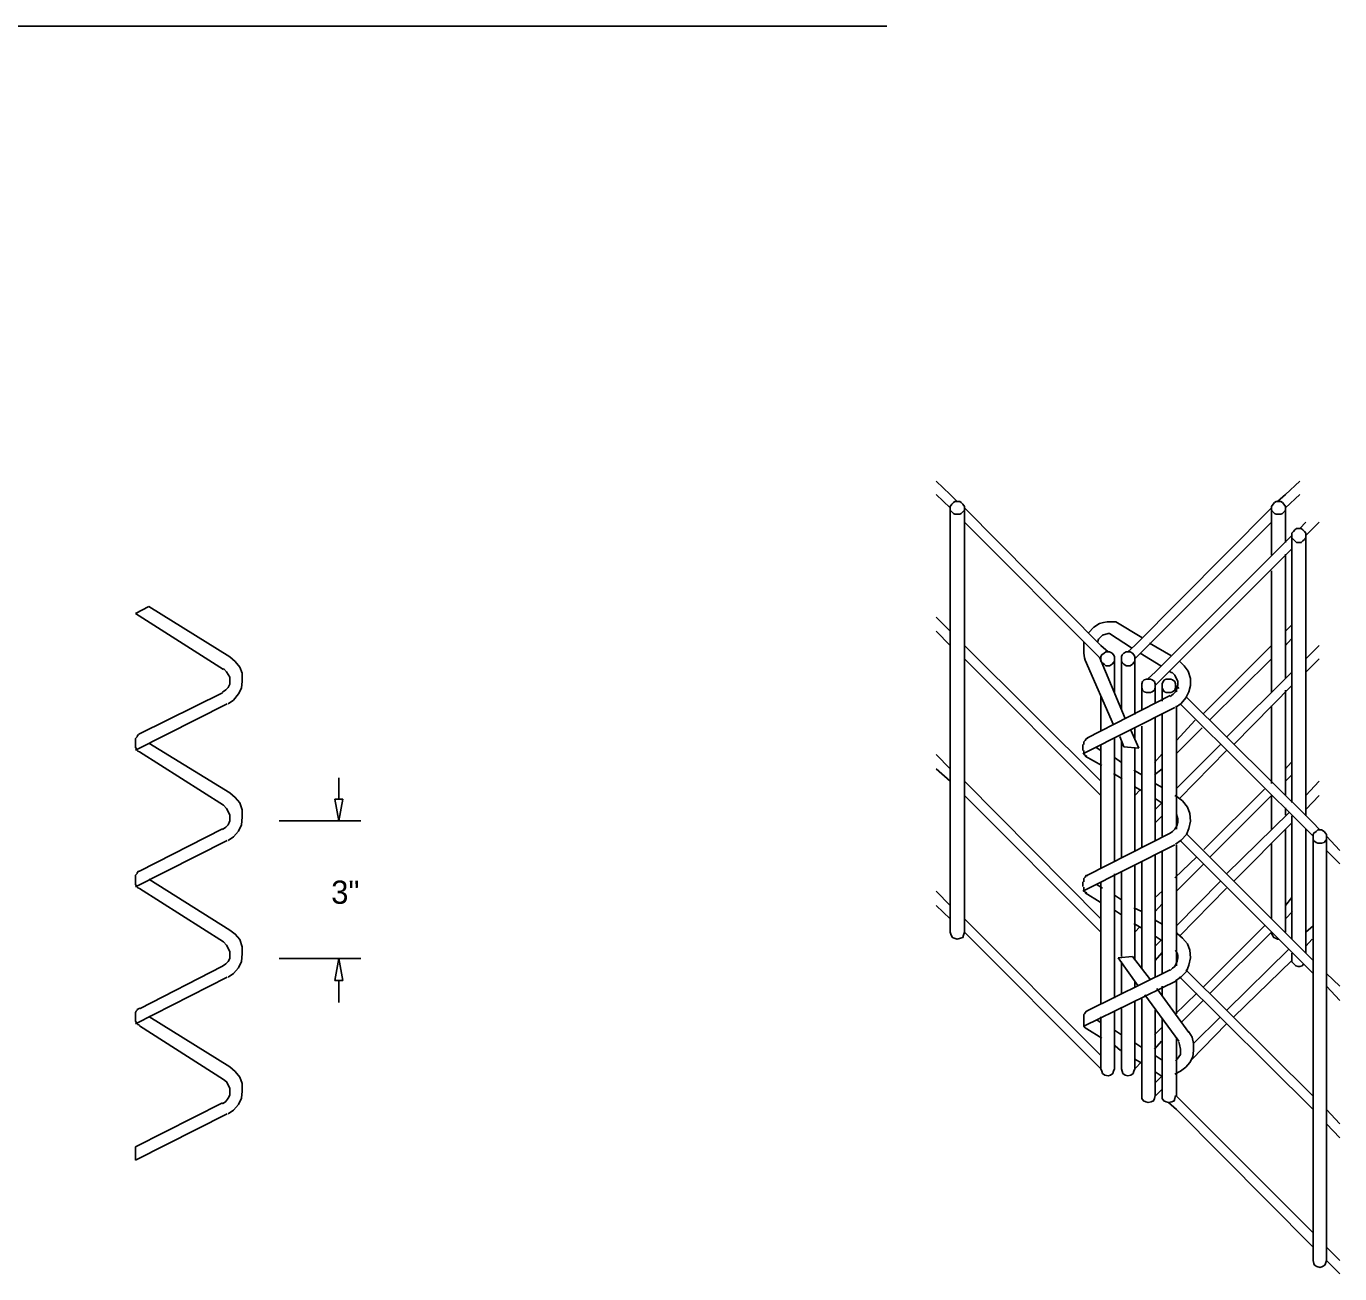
# Model space of a CAD drawing. Extents: x 3 to 3592, y -602 to 1171.
# Drawn here: x 2027.8 to 2197.8, y 836.8 to 998.1 of the extents above; entities that cross this region are included whole.
import ezdxf

# ---------------------------------------------------------------- set-up
doc = ezdxf.new("R2010")
doc.units = 0
for name, color, linetype in [('3', 7, 'Continuous'), ('H', 7, 'Continuous'), ('P', 7, 'Continuous')]:
    doc.layers.add(name, color=color, linetype=linetype)

msp = doc.modelspace()

# ---------------------------------------------------------------- linework, layer by layer
at = {"layer": '3'}
msp.add_line((1838.37, 998.15), (2139.16, 998.15), dxfattribs=at)
at = {"layer": 'H'}
for p, q in [((2067.77, 898.19), (2068.79, 898.19)), ((2068.28, 895.35), (2067.77, 898.19)), ((2068.79, 898.19), (2068.28, 895.35)), ((2068.28, 877.57), (2067.77, 874.72)), ((2068.79, 874.72), (2068.28, 877.57)), ((2067.77, 874.72), (2068.79, 874.72))]:
    msp.add_line(p, q, dxfattribs=at)
at = {"layer": 'P'}
for points in [[(2147.38, 937.57), (2145.55, 939.3)], [(2190.76, 937.57), (2192.59, 939.3)], [(2147.38, 935.84), (2145.55, 937.57)], [(2148.29, 936.66), (2147.38, 937.57)], [(2149.21, 935.84), (2149.21, 936.05), (2149, 936.35), (2148.8, 936.56), (2148.6, 936.66), (2147.99, 936.66), (2147.78, 936.56), (2147.58, 936.35), (2147.38, 936.05), (2147.38, 935.54), (2147.78, 935.13), (2147.99, 935.03), (2148.6, 935.03), (2148.8, 935.13), (2149.21, 935.54), (2149.21, 935.95)], [(2190.76, 935.84), (2190.76, 936.05), (2190.56, 936.35), (2190.35, 936.56), (2190.15, 936.66), (2189.54, 936.66), (2189.34, 936.56), (2189.14, 936.35), (2188.93, 936.05), (2188.93, 935.54), (2189.34, 935.13), (2189.54, 935.03), (2190.15, 935.03), (2190.35, 935.13), (2190.76, 935.54), (2190.76, 935.95)], [(2189.74, 936.66), (2190.76, 937.57)], [(2190.76, 935.84), (2192.59, 937.57)], [(2147.38, 882.71), (2147.38, 935.84)], [(2149.21, 882.71), (2149.21, 935.84)], [(2166.88, 918.06), (2149.21, 935.84)], [(2171.25, 918.06), (2188.93, 935.84)], [(2188.93, 929.75), (2188.93, 935.84)], [(2190.76, 931.37), (2190.76, 935.84)], [(2166.88, 916.34), (2149.21, 934.02)], [(2171.25, 916.34), (2188.93, 934.02)], [(2193.4, 932.29), (2193.4, 932.59), (2193.2, 932.8), (2193, 933), (2192.79, 933.2), (2192.18, 933.2), (2191.98, 933), (2191.78, 932.8), (2191.57, 932.59), (2191.57, 931.98), (2191.78, 931.78), (2191.98, 931.58), (2192.18, 931.37), (2192.79, 931.37), (2193, 931.58), (2193.2, 931.78), (2193.4, 931.98), (2193.4, 932.39)], [(2192.59, 933.2), (2193.4, 934.02)], [(2193.4, 932.29), (2195.13, 934.02)], [(2173.9, 914.61), (2191.57, 932.29)], [(2191.57, 897.74), (2191.57, 932.29)], [(2193.4, 896.02), (2193.4, 932.29)], [(2173.9, 912.88), (2191.57, 930.56)], [(2190.76, 913.8), (2190.76, 929.85)], [(2188.93, 911.97), (2188.93, 927.72)], [(2041.97, 922.17), (2043.69, 923.08)], [(2054.16, 916.58), (2043.69, 923.08)], [(2053.34, 914.96), (2041.97, 922.17)], [(2147.38, 919.89), (2145.55, 921.72)], [(2168.61, 921.11), (2167.7, 921.11), (2167.19, 921.01), (2166.68, 920.91), (2165.97, 920.4), (2165.26, 919.69)], [(2168.51, 921.11), (2168.82, 921.11)], [(2172.17, 919.08), (2168.82, 921.11)], [(2147.38, 918.06), (2145.55, 919.89)], [(2168, 919.59), (2167.8, 919.59), (2167.09, 919.39), (2166.88, 919.18), (2166.68, 918.98), (2166.58, 918.88), (2166.48, 918.57)], [(2170.85, 917.76), (2168, 919.59)], [(2190.76, 919.89), (2191.57, 920.71)], [(2166.88, 900.49), (2149.21, 918.06)], [(2164.65, 918.47), (2164.65, 918.17), (2164.65, 917.05), (2164.75, 916.44), (2164.85, 916.13)], [(2166.88, 918.06), (2167.8, 917.25)], [(2171.25, 918.06), (2170.34, 917.25)], [(2175.93, 916.74), (2173.18, 918.37)], [(2180.09, 909.23), (2188.93, 918.06)], [(2190.76, 918.06), (2191.47, 918.88)], [(2193.4, 916.34), (2195.13, 918.06)], [(2053.95, 910.49), (2054.67, 910.99), (2055.28, 911.81), (2055.68, 912.52), (2055.78, 913.43), (2055.78, 914.45), (2055.48, 915.26), (2054.87, 915.97), (2054.16, 916.58)], [(2166.88, 898.66), (2149.21, 916.34)], [(2164.85, 916.13), (2168.51, 907.8)], [(2166.68, 916.54), (2170.03, 908.62)], [(2168.61, 916.34), (2168.61, 916.64), (2168.51, 916.85), (2168.31, 917.05), (2168, 917.25), (2167.49, 917.25), (2167.29, 917.05), (2166.99, 916.85), (2166.88, 916.64), (2166.88, 916.03), (2166.99, 915.83), (2167.29, 915.63), (2167.49, 915.42), (2168, 915.42), (2168.31, 915.63), (2168.51, 915.83), (2168.61, 916.03), (2168.61, 916.54)], [(2166.88, 916.34), (2166.88, 916.03)], [(2168.61, 916.34), (2168.61, 911.87)], [(2171.25, 916.34), (2171.25, 916.64), (2171.15, 916.85), (2170.95, 917.05), (2170.64, 917.25), (2170.14, 917.25), (2169.83, 917.05), (2169.63, 916.85), (2169.53, 916.64), (2169.53, 916.03), (2169.63, 915.83), (2169.83, 915.63), (2170.14, 915.42), (2170.64, 915.42), (2170.95, 915.63), (2171.15, 915.83), (2171.25, 916.03), (2171.25, 916.54)], [(2169.53, 916.34), (2169.53, 909.83)], [(2171.25, 916.34), (2171.25, 909.12)], [(2174.61, 915.42), (2171.96, 917.05)], [(2176.54, 910.04), (2177.25, 910.55), (2177.86, 911.26), (2178.26, 912.07), (2178.47, 912.88), (2178.47, 913.8), (2178.16, 914.71), (2177.65, 915.42), (2177.04, 916.03)], [(2180.91, 908.41), (2188.93, 916.34)], [(2193.4, 914.61), (2195.13, 916.34)], [(2053.24, 912.01), (2053.65, 912.31), (2053.95, 912.62), (2054.16, 913.03), (2054.16, 913.43), (2054.16, 913.94), (2053.75, 914.65), (2053.34, 915.06)], [(2173.9, 914.61), (2172.98, 913.8)], [(2176.03, 914.51), (2175.72, 914.71)], [(2175.83, 911.46), (2176.23, 911.77), (2176.54, 912.07), (2176.74, 912.58), (2176.84, 912.98), (2176.84, 913.39), (2176.44, 914.2), (2176.03, 914.61)], [(2183.14, 906.18), (2191.57, 914.61)], [(2173.9, 912.88), (2173.9, 913.09), (2173.79, 913.39), (2173.49, 913.59), (2173.29, 913.7), (2172.78, 913.7), (2172.47, 913.59), (2172.27, 913.39), (2172.17, 913.09), (2172.17, 912.58), (2172.27, 912.27), (2172.47, 912.07), (2172.78, 911.97), (2173.29, 911.97), (2173.49, 912.07), (2173.79, 912.27), (2173.9, 912.58), (2173.9, 912.98)], [(2172.17, 912.88), (2172.17, 909.63)], [(2173.9, 912.88), (2173.9, 910.55)], [(2176.54, 912.88), (2176.54, 913.09), (2176.44, 913.39), (2176.13, 913.59), (2175.93, 913.7), (2175.32, 913.7), (2175.11, 913.59), (2174.91, 913.39), (2174.81, 913.09), (2174.81, 912.58), (2174.91, 912.27), (2175.11, 912.07), (2175.32, 911.97), (2175.93, 911.97), (2176.13, 912.07), (2176.44, 912.27), (2176.54, 912.58), (2176.54, 912.98)], [(2174.81, 912.88), (2174.81, 910.85)], [(2176.64, 912.88), (2176.94, 912.48)], [(2176.64, 912.88), (2176.64, 912.07)], [(2184.06, 905.26), (2191.57, 912.88)], [(2042.47, 906.63), (2053.24, 911.91)], [(2165.06, 906.08), (2175.83, 911.56)], [(2166.88, 911.56), (2166.88, 907.09)], [(2177.96, 911.36), (2194.32, 895.1)], [(2190.76, 898.66), (2190.76, 912.27)], [(2041.97, 904.49), (2053.85, 910.49)], [(2164.55, 904.04), (2176.44, 910.04)], [(2176.64, 910.24), (2176.64, 894.29)], [(2177.15, 910.44), (2194.32, 893.38)], [(2188.93, 900.18), (2188.93, 910.24)], [(2172.17, 907.6), (2172.17, 891.95)], [(2173.9, 908.72), (2173.9, 892.77)], [(2174.81, 909.12), (2174.81, 893.38)], [(2176.64, 905.77), (2179.08, 908.41)], [(2042.47, 906.63), (2042.37, 906.52), (2042.17, 906.32), (2042.17, 906.22), (2042.07, 906.12), (2041.97, 906.02), (2041.97, 905.81)], [(2041.97, 905), (2041.97, 905.81)], [(2165.16, 906.08), (2164.95, 905.97), (2164.85, 905.77), (2164.75, 905.67), (2164.65, 905.57), (2164.65, 905.47), (2164.65, 905.26)], [(2168.61, 906.08), (2168.61, 890.12)], [(2169.32, 906.28), (2169.83, 904.96)], [(2169.53, 905.77), (2169.53, 890.63)], [(2170.75, 907.09), (2171.76, 904.75)], [(2171.25, 907.4), (2171.25, 905.87)], [(2176.74, 904.15), (2179.99, 907.4)], [(2041.97, 905), (2041.97, 904.8), (2042.07, 904.8), (2042.07, 904.59), (2042.27, 904.39), (2042.47, 904.29)], [(2053.34, 897.38), (2042.47, 904.29)], [(2054.16, 899.01), (2043.69, 905.41)], [(2164.55, 904.45), (2164.55, 905.26)], [(2164.65, 904.45), (2164.65, 904.25), (2164.65, 904.25), (2164.65, 904.04), (2164.85, 903.84), (2165.06, 903.74)], [(2166.88, 904.45), (2166.28, 904.86)], [(2166.88, 905.26), (2166.88, 889.21)], [(2171.76, 904.75), (2169.83, 904.96)], [(2171.25, 904.75), (2171.25, 891.45)], [(2176.64, 899.57), (2182.33, 905.26)], [(2177.04, 898.25), (2183.14, 904.45)], [(2147.38, 902.11), (2145.55, 903.94)], [(2166.99, 902.52), (2164.85, 903.74)], [(2169.53, 902.93), (2168.61, 903.54)], [(2173.79, 902.93), (2174.81, 904.04)], [(2190.76, 902.11), (2191.47, 902.93)], [(2068.28, 898.19), (2068.28, 900.94)], [(2147.38, 900.49), (2145.55, 902.11)], [(2169.63, 900.79), (2168.51, 901.5)], [(2172.17, 901.3), (2171.15, 901.91)], [(2173.79, 901.3), (2174.81, 902.11)], [(2190.76, 900.49), (2191.57, 901.3)], [(2053.95, 892.81), (2054.67, 893.32), (2055.28, 894.03), (2055.68, 894.84), (2055.78, 895.86), (2055.78, 896.77), (2055.48, 897.68), (2054.87, 898.4), (2054.16, 899.01)], [(2166.88, 882.71), (2149.21, 900.49)], [(2172.17, 899.27), (2171.25, 899.78)], [(2171.25, 898.66), (2171.96, 899.37)], [(2174.81, 899.67), (2173.9, 900.18)], [(2180.19, 891.65), (2188.02, 899.47)], [(2193.4, 898.66), (2195.13, 900.49)], [(2053.24, 894.23), (2053.65, 894.53), (2053.95, 894.84), (2054.16, 895.35), (2054.16, 895.75), (2054.16, 896.16), (2053.75, 896.97), (2053.34, 897.38)], [(2166.88, 880.98), (2149.21, 898.66)], [(2174.81, 897.64), (2173.9, 898.25)], [(2173.9, 896.83), (2174.81, 897.74)], [(2176.74, 898.46), (2176.44, 898.66)], [(2176.54, 892.36), (2177.25, 892.87), (2177.96, 893.58), (2178.26, 894.39), (2178.47, 895.31), (2178.37, 896.32), (2178.06, 897.13), (2177.45, 897.95), (2176.74, 898.46)], [(2181.01, 890.73), (2188.93, 898.66)], [(2188.93, 894.19), (2188.93, 898.56)], [(2193.4, 896.83), (2195.13, 898.66)], [(2173.9, 895.1), (2174.81, 896.02)], [(2175.83, 893.78), (2176.13, 893.99), (2176.44, 894.29), (2176.74, 894.8), (2176.84, 895.2), (2176.84, 895.61), (2176.74, 895.92), (2176.64, 896.32)], [(2183.14, 888.5), (2191.17, 896.42)], [(2190.76, 896.12), (2190.76, 897.03)], [(2191.57, 880.07), (2191.57, 896.02)], [(2042.47, 888.85), (2053.24, 894.33)], [(2060.56, 895.35), (2071.12, 895.35)], [(2176.64, 895.1), (2176.74, 894.8)], [(2184.06, 887.58), (2191.57, 895.1)], [(2190.76, 882.71), (2190.76, 894.29)], [(2193.4, 879.15), (2193.4, 894.29)], [(2195.13, 894.29), (2194.32, 895.1)], [(2196.04, 893.27), (2196.04, 893.58), (2195.94, 893.78), (2195.74, 893.99), (2195.43, 894.19), (2194.93, 894.19), (2194.72, 893.99), (2194.42, 893.78), (2194.32, 893.58), (2194.32, 892.97), (2194.42, 892.77), (2194.72, 892.56), (2194.93, 892.46), (2195.43, 892.46), (2195.74, 892.56), (2195.94, 892.77), (2196.04, 892.97), (2196.04, 893.48)], [(2041.97, 886.81), (2053.85, 892.81)], [(2164.55, 886.26), (2176.44, 892.26)], [(2165.06, 888.3), (2175.83, 893.78)], [(2176.64, 892.26), (2176.64, 876.61)], [(2177.15, 892.77), (2194.32, 875.6)], [(2177.96, 893.68), (2194.32, 877.32)], [(2188.93, 882.71), (2188.93, 892.46)], [(2194.32, 840.24), (2194.32, 893.38)], [(2196.04, 840.24), (2196.04, 893.38)], [(2196.04, 893.38), (2197.77, 891.55)], [(2173.9, 890.94), (2173.9, 875.09)], [(2174.81, 891.45), (2174.81, 875.6)], [(2176.44, 887.99), (2179.28, 890.73)], [(2196.04, 891.55), (2197.77, 889.82)], [(2042.47, 888.85), (2042.37, 888.85), (2042.17, 888.64), (2042.17, 888.54), (2042.07, 888.44), (2041.97, 888.34), (2041.97, 888.03)], [(2169.53, 888.8), (2169.53, 877.83)], [(2171.25, 889.62), (2171.25, 877.53)], [(2172.17, 890.12), (2172.17, 876.31)], [(2176.64, 886.26), (2180.09, 889.72)], [(2041.97, 887.22), (2041.97, 888.03)], [(2041.97, 887.32), (2041.97, 887.12), (2042.07, 887.02), (2042.07, 886.91), (2042.27, 886.71), (2042.47, 886.61)], [(2054.16, 881.23), (2043.69, 887.83)], [(2164.55, 886.87), (2164.55, 887.48)], [(2165.16, 888.3), (2164.95, 888.3), (2164.85, 888.09), (2164.75, 887.99), (2164.65, 887.89), (2164.65, 887.79), (2164.65, 887.48)], [(2167.09, 886.67), (2166.28, 887.18)], [(2166.88, 887.48), (2166.88, 871.63)], [(2168.61, 888.5), (2168.61, 872.45)], [(2176.64, 881.79), (2182.33, 887.58)], [(2053.34, 879.7), (2042.47, 886.61)], [(2147.38, 884.43), (2145.55, 886.26)], [(2164.65, 886.77), (2164.65, 886.57), (2164.65, 886.47), (2164.65, 886.37), (2164.85, 886.16), (2165.06, 886.06)], [(2166.78, 884.84), (2164.85, 886.06)], [(2169.53, 885.15), (2168.61, 885.76)], [(2173.9, 885.45), (2174.81, 886.26)], [(2177.04, 880.47), (2183.14, 886.67)], [(2190.76, 884.43), (2191.57, 885.45)], [(2147.38, 882.71), (2145.55, 884.43)], [(2169.53, 883.22), (2168.61, 883.83)], [(2172.17, 883.62), (2171.15, 884.13)], [(2173.9, 883.62), (2174.81, 884.64)], [(2147.38, 882.71), (2147.38, 880.98)], [(2166.88, 865.03), (2149.21, 882.71)], [(2149.21, 882.71), (2149.21, 880.98)], [(2172.17, 881.49), (2171.15, 882.1)], [(2174.81, 882), (2173.9, 882.5)], [(2190.76, 882.71), (2191.68, 883.62)], [(2190.76, 882.71), (2190.76, 880.98)], [(2053.95, 875.13), (2054.67, 875.64), (2055.28, 876.35), (2055.68, 877.16), (2055.78, 878.18), (2055.78, 879.09), (2055.48, 880.01), (2054.87, 880.72), (2054.16, 881.23)], [(2147.38, 880.98), (2147.48, 880.57), (2147.68, 880.27), (2147.89, 880.17), (2148.29, 880.07), (2148.7, 880.17), (2149, 880.27), (2149.1, 880.57), (2149.21, 880.98)], [(2166.88, 863.3), (2149.21, 880.98)], [(2171.25, 880.98), (2171.96, 881.69)], [(2174.81, 879.86), (2173.9, 880.47)], [(2176.54, 874.68), (2177.25, 875.19), (2177.96, 875.9), (2178.26, 876.71), (2178.47, 877.63), (2178.37, 878.64), (2178.06, 879.46), (2177.45, 880.17), (2176.74, 880.78)], [(2176.74, 880.78), (2176.64, 880.98)], [(2180.09, 873.87), (2188.02, 881.79)], [(2181.01, 873.06), (2188.93, 880.98)], [(2188.93, 880.98), (2188.93, 880.78), (2189.24, 880.27), (2189.44, 880.17), (2189.74, 880.07), (2189.85, 880.07)], [(2190.66, 880.98), (2190.76, 880.98)], [(2193.4, 880.98), (2194.32, 881.79)], [(2053.24, 876.55), (2053.65, 876.86), (2053.95, 877.16), (2054.16, 877.57), (2054.16, 878.08), (2054.16, 878.48), (2053.75, 879.29), (2053.34, 879.7)], [(2173.9, 879.15), (2174.71, 879.96)], [(2175.83, 876), (2176.13, 876.31), (2176.44, 876.51), (2176.74, 877.22), (2176.84, 877.63), (2176.84, 877.93), (2176.74, 878.24), (2176.54, 878.64)], [(2183.14, 870.82), (2191.17, 878.75)], [(2193.4, 879.15), (2194.22, 880.07)], [(2193.4, 879.15), (2193.4, 878.24)], [(2060.56, 877.57), (2071.12, 877.57)], [(2169.12, 877.63), (2170.95, 877.83)], [(2171.66, 874.07), (2169.12, 877.63)], [(2169.53, 877.12), (2169.53, 872.95)], [(2173.29, 874.78), (2170.95, 877.83)], [(2173.9, 877.32), (2174.81, 878.34)], [(2176.64, 877.32), (2176.74, 877.22)], [(2184.06, 870.01), (2191.57, 877.32)], [(2191.57, 878.24), (2191.57, 877.32)], [(2191.57, 877.42), (2191.57, 877.12), (2191.78, 876.92), (2191.88, 876.81), (2192.08, 876.61), (2192.39, 876.51), (2192.59, 876.51), (2192.89, 876.61), (2193.1, 876.81)], [(2042.47, 871.07), (2053.24, 876.55)], [(2165.16, 870.82), (2175.83, 876.1)], [(2177.04, 875.19), (2194.32, 858.02)], [(2177.86, 876.1), (2194.32, 859.75)], [(2196.04, 875.6), (2197.77, 873.97)], [(2041.97, 869.13), (2053.85, 875.13)], [(2068.28, 874.72), (2068.28, 871.88)], [(2164.65, 868.79), (2176.64, 874.68)], [(2171.25, 874.68), (2171.25, 873.77)], [(2178.26, 867.98), (2174.1, 873.67)], [(2174.81, 873.97), (2174.81, 872.75)], [(2176.64, 874.78), (2176.64, 870.41)], [(2196.04, 873.97), (2197.77, 872.14)], [(2171.25, 872.04), (2171.25, 863.3)], [(2172.17, 872.34), (2172.17, 859.75)], [(2176.94, 866.86), (2172.57, 872.85)], [(2176.44, 870.31), (2179.28, 873.06)], [(2177.25, 869.3), (2180.09, 872.14)], [(2042.47, 871.17), (2042.37, 871.07), (2042.17, 870.96), (2042.17, 870.86), (2042.07, 870.76), (2041.97, 870.56), (2041.97, 870.35)], [(2041.97, 869.64), (2041.97, 870.35)], [(2165.16, 870.82), (2164.95, 870.72), (2164.85, 870.52), (2164.75, 870.41), (2164.65, 870.31), (2164.65, 870.21), (2164.65, 870.01)], [(2168.61, 870.72), (2168.61, 863.3)], [(2169.53, 871.13), (2169.53, 863.3)], [(2173.9, 870.92), (2173.9, 859.75)], [(2041.97, 869.64), (2041.97, 869.44), (2042.07, 869.34), (2042.07, 869.24), (2042.27, 869.03), (2042.47, 868.93)], [(2053.34, 861.92), (2042.47, 868.83)], [(2054.16, 863.55), (2043.69, 870.05)], [(2164.65, 869.19), (2164.65, 870.01)], [(2164.65, 869.19), (2164.65, 868.99), (2164.65, 868.99), (2164.65, 868.79), (2164.85, 868.59), (2165.06, 868.48)], [(2166.99, 867.26), (2165.06, 868.48)], [(2166.88, 869.3), (2166.38, 869.6)], [(2166.88, 870.01), (2166.88, 863.3)], [(2173.79, 867.67), (2174.71, 868.59)], [(2174.81, 869.7), (2174.81, 859.75)], [(2178.57, 864.42), (2183.14, 869.09)], [(2178.87, 866.55), (2182.33, 870.01)], [(2169.53, 867.67), (2168.61, 868.28)], [(2173.79, 865.84), (2174.71, 866.86)], [(2176.44, 862.59), (2177.15, 863), (2177.86, 863.51), (2178.37, 864.11), (2178.77, 864.83), (2178.87, 865.64), (2178.87, 866.55), (2178.67, 867.37), (2178.26, 868.08)], [(2176.54, 864.32), (2176.74, 864.52), (2176.94, 864.83), (2177.15, 865.13), (2177.15, 865.54), (2177.15, 865.84), (2177.04, 866.45), (2176.94, 866.76)], [(2176.64, 867.37), (2176.64, 859.75)], [(2169.42, 865.64), (2168.71, 866.25)], [(2172.17, 866.05), (2171.25, 866.65)], [(2174.81, 864.42), (2173.9, 865.03)], [(2053.95, 857.45), (2054.67, 857.96), (2055.28, 858.67), (2055.68, 859.48), (2055.78, 860.4), (2055.78, 861.41), (2055.48, 862.23), (2054.87, 862.94), (2054.16, 863.55)], [(2166.88, 863.3), (2166.99, 863), (2167.09, 862.69), (2167.39, 862.49), (2167.8, 862.39), (2168.1, 862.49), (2168.41, 862.69), (2168.51, 863), (2168.61, 863.3)], [(2169.53, 863.3), (2169.63, 863), (2169.73, 862.69), (2170.03, 862.49), (2170.34, 862.39), (2170.75, 862.49), (2171.05, 862.69), (2171.15, 863), (2171.25, 863.3)], [(2172.17, 864.01), (2171.25, 864.52)], [(2171.25, 863.3), (2172.17, 864.22)], [(2053.24, 858.77), (2053.65, 859.08), (2053.95, 859.48), (2054.16, 859.89), (2054.16, 860.4), (2054.16, 860.8), (2053.75, 861.62), (2053.34, 861.92)], [(2174.81, 862.29), (2173.9, 862.9)], [(2173.9, 861.47), (2174.81, 862.39)], [(2173.9, 859.75), (2174.81, 860.66)], [(2041.97, 853.18), (2053.24, 858.87)], [(2172.17, 859.85), (2172.17, 859.44), (2172.37, 859.14), (2172.68, 859.03), (2172.98, 858.93), (2173.39, 859.03), (2173.69, 859.14), (2173.79, 859.44), (2173.9, 859.85)], [(2174.81, 859.85), (2174.81, 859.44), (2175.01, 859.14), (2175.32, 859.03), (2175.62, 858.93), (2176.03, 859.03), (2176.33, 859.14), (2176.44, 859.44), (2176.54, 859.85)], [(2176.64, 858.02), (2175.62, 858.93)], [(2176.64, 859.75), (2194.32, 842.07)], [(2041.97, 851.46), (2053.85, 857.45)], [(2176.64, 858.02), (2194.32, 840.24)], [(2196.04, 858.02), (2197.77, 856.19)], [(2196.04, 856.19), (2197.77, 854.36)], [(2041.97, 851.46), (2041.97, 853.18)], [(2194.32, 840.24), (2194.32, 838.51)], [(2196.04, 840.24), (2197.77, 838.51)], [(2196.04, 840.24), (2196.04, 838.51)], [(2194.32, 838.51), (2194.42, 838.11), (2194.52, 837.9), (2194.82, 837.7), (2195.23, 837.6), (2195.54, 837.7), (2195.84, 837.9), (2195.94, 838.11), (2196.04, 838.51)], [(2196.04, 838.51), (2197.77, 836.78)]]:
    msp.add_lwpolyline(points, dxfattribs=at)

# ---------------------------------------------------------------- texts
at = {"layer": '3'}
msp.add_text('3"', height=3, dxfattribs=at).set_placement((2067.29, 884.64))

doc.saveas('drawing.dxf')
